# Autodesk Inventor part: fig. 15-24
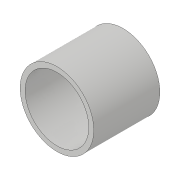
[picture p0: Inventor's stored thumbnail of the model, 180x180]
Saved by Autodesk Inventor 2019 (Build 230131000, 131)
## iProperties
Created: 2018-03
Part Number: fig. 15-24
Material: Generic
Document SubType Name: Modeling
Designer: CADCIM 00
Density: 1 g/cm^3
Appearance: Default
Author: CADCIM 00
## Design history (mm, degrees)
sketch "Sketch1"
  geometry: C1 r 14.209 at (0.32, 0); C2 r 12.286 at (0.32, 0); 1 further point
  constraints: 2 centre point, 1 coincident
  dimensions: "d0" = 25.5 dimension on point (0, 0) C1.centre C1 C2.centre C2
extrude "Extrusion1" new body sketch "Sketch1" distance "d0" = 25.5; taper "d1" = 0 deg
body "Solid1"
